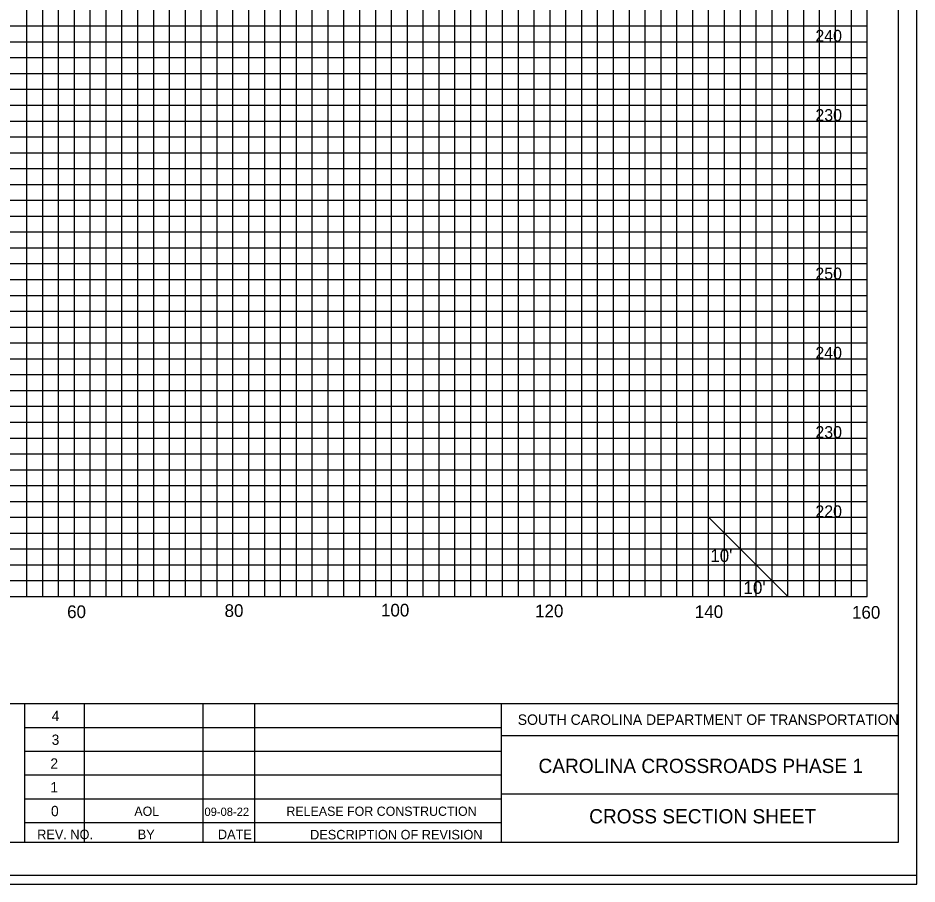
# Model space of a CAD drawing. Extents: x 967 to 1326, y 964 to 2304.
# Drawn here: x 1212.9 to 1326.3, y 2083.7 to 2193 of the extents above; entities that cross this region are included whole.
import ezdxf

# ---------------------------------------------------------------- set-up
doc = ezdxf.new("R2010")
doc.units = 0
for name, color, linetype in [('Default', 7, 'Continuous'), ('RD_GPK_XS_Cell', 7, 'Continuous'), ('RD_PD_PaveShd', 7, 'Continuous'), ('RD_XS_ExGround', 7, 'Continuous'), ('RD_XS_ExPaveRet', 7, 'Continuous'), ('RD_XS_Misc_Line', 7, 'Continuous'), ('RD_XS_PaveOvlay', 7, 'Continuous'), ('RD_XS_TX_Elev_EX', 7, 'Continuous')]:
    doc.layers.add(name, color=color, linetype=linetype)

msp = doc.modelspace()

# ---------------------------------------------------------------- linework, layer by layer
at = {"layer": 'RD_GPK_XS_Cell'}
for p, q in [((1220, 2120), (1220, 2290)), ((1230, 2120), (1230, 2290)), ((1240, 2120), (1240, 2290)), ((1250, 2120), (1250, 2290)), ((1260, 2120), (1260, 2290)), ((1270, 2120), (1270, 2290)), ((1280, 2120), (1280, 2290)), ((1290, 2120), (1290, 2290)), ((1300, 2120), (1300, 2290)), ((1310, 2120), (1310, 2290)), ((1320, 2120), (1320, 2290)), ((1000, 2190), (1320, 2190)), ((1000, 2180), (1320, 2180)), ((1000, 2170), (1320, 2170)), ((1000, 2160), (1320, 2160)), ((1000, 2150), (1320, 2150)), ((1000, 2140), (1320, 2140)), ((1000, 2130), (1320, 2130)), ((1000, 2120), (1320, 2120))]:
    msp.add_line(p, q, dxfattribs=at)
at = {"layer": 'RD_PD_PaveShd'}
for p, q in [((1323.89, 2298.46), (1323.89, 2088.98)), ((996.11, 2106.49), (1323.89, 2106.49)), ((1213.76, 2088.94), (1213.76, 2106.49)), ((1221.26, 2088.95), (1221.26, 2106.48)), ((1236.26, 2088.95), (1236.26, 2106.48)), ((1242.76, 2088.95), (1242.76, 2106.48)), ((1273.88, 2088.98), (1273.88, 2106.49)), ((1213.76, 2103.48), (1273.88, 2103.48)), ((1323.93, 2102.43), (1273.88, 2102.43)), ((1213.76, 2100.48), (1273.88, 2100.48)), ((1213.76, 2097.48), (1273.88, 2097.48)), ((1323.89, 2095.04), (1273.88, 2095.04)), ((1213.76, 2094.48), (1273.88, 2094.48)), ((1213.76, 2091.48), (1273.88, 2091.48)), ((1323.89, 2088.98), (996.11, 2088.98))]:
    msp.add_line(p, q, dxfattribs=at)
at = {"layer": 'RD_XS_ExGround'}
for p, q in [((1214, 2120), (1214, 2290)), ((1216, 2120), (1216, 2290)), ((1218, 2120), (1218, 2290)), ((1222, 2120), (1222, 2290)), ((1224, 2120), (1224, 2290)), ((1226, 2120), (1226, 2290)), ((1228, 2120), (1228, 2290)), ((1232, 2120), (1232, 2290)), ((1234, 2120), (1234, 2290)), ((1236, 2120), (1236, 2290)), ((1238, 2120), (1238, 2290)), ((1242, 2120), (1242, 2290)), ((1244, 2120), (1244, 2290)), ((1246, 2120), (1246, 2290)), ((1248, 2120), (1248, 2290)), ((1252, 2120), (1252, 2290)), ((1254, 2120), (1254, 2290)), ((1256, 2120), (1256, 2290)), ((1258, 2120), (1258, 2290)), ((1262, 2120), (1262, 2290)), ((1264, 2120), (1264, 2290)), ((1266, 2120), (1266, 2290)), ((1268, 2120), (1268, 2290)), ((1272, 2120), (1272, 2290)), ((1274, 2120), (1274, 2290)), ((1276, 2120), (1276, 2290)), ((1278, 2120), (1278, 2290)), ((1282, 2120), (1282, 2290)), ((1284, 2120), (1284, 2290)), ((1286, 2120), (1286, 2290)), ((1288, 2120), (1288, 2290)), ((1292, 2120), (1292, 2290)), ((1294, 2120), (1294, 2290)), ((1296, 2120), (1296, 2290)), ((1298, 2120), (1298, 2290)), ((1302, 2120), (1302, 2290)), ((1304, 2120), (1304, 2290)), ((1306, 2120), (1306, 2290)), ((1308, 2120), (1308, 2290)), ((1312, 2120), (1312, 2290)), ((1314, 2120), (1314, 2290)), ((1316, 2120), (1316, 2290)), ((1318, 2120), (1318, 2290)), ((1000, 2192), (1320, 2192)), ((1000, 2188), (1320, 2188)), ((1000, 2186), (1320, 2186)), ((1000, 2184), (1320, 2184)), ((1000, 2182), (1320, 2182)), ((1000, 2178), (1320, 2178)), ((1000, 2176), (1320, 2176)), ((1000, 2174), (1320, 2174)), ((1000, 2172), (1320, 2172)), ((1000, 2168), (1320, 2168)), ((1000, 2166), (1320, 2166)), ((1000, 2164), (1320, 2164)), ((1000, 2162), (1320, 2162)), ((1000, 2158), (1320, 2158)), ((1000, 2156), (1320, 2156)), ((1000, 2154), (1320, 2154)), ((1000, 2152), (1320, 2152)), ((1000, 2148), (1320, 2148)), ((1000, 2146), (1320, 2146)), ((1000, 2144), (1320, 2144)), ((1000, 2142), (1320, 2142)), ((1000, 2138), (1320, 2138)), ((1000, 2136), (1320, 2136)), ((1000, 2134), (1320, 2134)), ((1000, 2132), (1320, 2132)), ((1000, 2128), (1320, 2128)), ((1000, 2126), (1320, 2126)), ((1000, 2124), (1320, 2124)), ((1000, 2122), (1320, 2122))]:
    msp.add_line(p, q, dxfattribs=at)
at = {"layer": 'RD_XS_ExPaveRet'}
msp.add_line((1300, 2130), (1310, 2120), dxfattribs=at)
at = {"layer": 'RD_XS_PaveOvlay'}
msp.add_lwpolyline([(967.41, 2083.72), (1326.28, 2083.72), (1326.28, 2303.72), (967.41, 2303.72)], close=True, dxfattribs=at)
at = {"layer": 'RD_XS_TX_Elev_EX'}
for points in [[(967.41, 2083.72), (1326.28, 2083.72), (1326.28, 2303.72), (967.41, 2303.72)], [(988.52, 2084.84), (1326.28, 2084.84), (1326.28, 2302.6), (988.52, 2302.6)]]:
    msp.add_lwpolyline(points, close=True, dxfattribs=at)

# ---------------------------------------------------------------- texts
at = {"layer": 'Default'}
for s, p in [('240', (1313.47, 2190)), ('230', (1313.47, 2180)), ('250', (1313.47, 2160)), ('240', (1313.47, 2150)), ('230', (1313.47, 2140)), ('220', (1313.47, 2130))]:
    msp.add_text(s, height=1.5, dxfattribs=at).set_placement(p)
at = {"layer": 'RD_XS_ExPaveRet'}
for s, height, p in [("10'", 1.6, (1300.21, 2124.36)), ("10'", 1.6, (1304.4, 2120.32)), ('60', 1.6, (1219.08, 2117.28)), ('80', 1.6, (1238.94, 2117.42)), ('100', 1.6, (1258.67, 2117.48)), ('120', 1.6, (1278.11, 2117.38)), ('140', 1.6, (1298.26, 2117.29)), ('160', 1.6, (1318.08, 2117.2)), ('4', 1.3, (1217.13, 2104.28)), ('SOUTH CAROLINA DEPARTMENT OF TRANSPORTATION', 1.32, (1275.92, 2103.8)), ('3', 1.3, (1217.13, 2101.28)), ('2', 1.3, (1216.97, 2098.28)), ('1', 1.3, (1216.97, 2095.28)), ('0', 1.3, (1217.05, 2092.28)), ('REV. NO.', 1.2, (1215.3, 2089.38)), ('BY', 1.2, (1227.99, 2089.38)), ('DATE', 1.2, (1238.1, 2089.38)), ('DESCRIPTION OF REVISION', 1.2, (1249.73, 2089.35))]:
    msp.add_text(s, height=height, dxfattribs=at).set_placement(p)
for s, p in [('CAROLINA CROSSROADS PHASE 1', (1278.54, 2097.73)), ('CROSS SECTION SHEET', (1284.93, 2091.37))]:
    msp.add_text(s, height=1.8, rotation=0, dxfattribs=at).set_placement(p)
at = {"layer": 'RD_XS_Misc_Line'}
for s, height, p in [('AOL', 1.17, (1227.56, 2092.32)), ('RELEASE FOR CONSTRUCTION', 1.17, (1246.74, 2092.32)), ('09-08-22', 1.053, (1236.4, 2092.31))]:
    msp.add_text(s, height=height, dxfattribs=at).set_placement(p)

doc.saveas('drawing.dxf')
